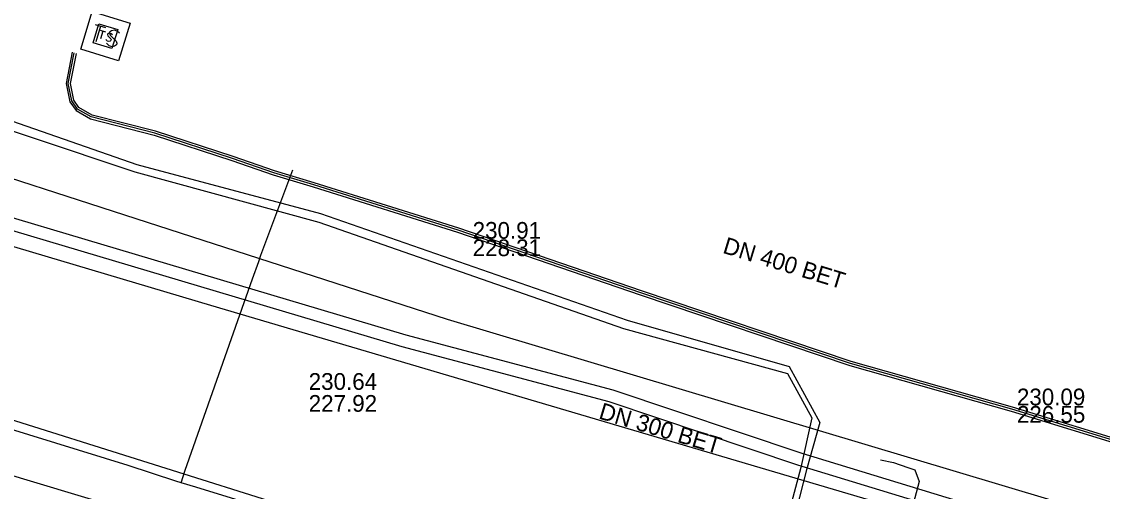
# Model space of a CAD drawing. Extents: x -599951 to -598963, y -1164095 to -1162939.
# Drawn here: x -599654.3 to -599602.6, y -1164052.7 to -1164030.3 of the extents above; entities that cross this region are included whole.
import ezdxf

# ---------------------------------------------------------------- set-up
doc = ezdxf.new("R2010")
doc.units = 0
for name, color, linetype in [('25', 7, 'Continuous'), ('Level 3', 7, 'Continuous'), ('Vrstva 1', 7, 'Continuous'), ('Vrstva 12', 7, 'Continuous'), ('Vrstva 13', 7, 'Continuous'), ('Vrstva 16', 7, 'Continuous'), ('Vrstva 19', 7, 'Continuous'), ('Vrstva 4', 7, 'Continuous'), ('Vrstva 42', 7, 'Continuous'), ('Vrstva 43', 7, 'Continuous'), ('Vrstva 44', 7, 'Continuous'), ('Vrstva 45', 7, 'Continuous'), ('Vrstva 5', 7, 'Continuous'), ('Vrstva 8', 7, 'Continuous')]:
    doc.layers.add(name, color=color, linetype=linetype)

# ---------------------------------------------------------------- blocks, each defined once
blk = doc.blocks.new('VN640')
at = {"layer": '25'}
for points in [[(-1.89, 1.889), (1.889, 1.889)], [(-1.89, -1.89), (-1.89, 1.889)], [(-1.26, 0.787), (-0.221, 0.787)], [(-0.725, 0.787), (-0.725, -0.788)], [(1.197, 0.661), (0.945, 0.787), (0.661, 0.787), (0.409, 0.661), (0.283, 0.472), (0.283, 0.409), (0.409, 0.22), (1.133, -0.158), (1.259, -0.316), (1.259, -0.473), (1.133, -0.662), (0.913, -0.788), (0.629, -0.788), (0.503, -0.725), (0.283, -0.599)], [(1.889, 1.889), (1.889, -1.89)], [(1.889, -1.89), (-1.89, -1.89)]]:
    blk.add_lwpolyline(points, dxfattribs=at)
blk = doc.blocks.new('NN640')
at = {"layer": '25'}
for points in [[(-1.89, 1.889), (1.889, 1.889)], [(-1.89, -1.89), (-1.89, 1.889)], [(1.889, 1.889), (1.889, -1.89)], [(-1.26, 0.787), (-0.221, 0.787)], [(-0.725, 0.787), (-0.725, -0.788)], [(1.197, 0.661), (0.945, 0.787), (0.661, 0.787), (0.409, 0.661), (0.283, 0.472), (0.283, 0.409), (0.409, 0.22), (1.133, -0.158), (1.259, -0.316), (1.259, -0.473), (1.133, -0.662), (0.913, -0.788), (0.629, -0.788), (0.503, -0.725), (0.283, -0.599)], [(1.889, -1.89), (-1.89, -1.89)]]:
    blk.add_lwpolyline(points, dxfattribs=at)

msp = doc.modelspace()

# ---------------------------------------------------------------- linework, layer by layer
at = {"layer": 'Level 3'}
msp.add_lwpolyline([(-599670.761, -1164034.874), (-599635.968, -1164045.241), (-599626.064, -1164047.883), (-599617.019, -1164050.914), (-599600, -1164056.104), (-599591.155, -1164058.802), (-599583.98, -1164060.87), (-599584.17, -1164061.41), (-599591.325, -1164059.378), (-599600, -1164056.732), (-599617.201, -1164051.486), (-599626.236, -1164048.457), (-599636.132, -1164045.819), (-599670.939, -1164035.446)], dxfattribs=at)
at = {"layer": 'Vrstva 1'}
msp.add_line((-599684.011, -1164040.127), (-599641.114, -1164053.622), dxfattribs=at)
at = {"layer": 'Vrstva 12'}
for points in [[(-599611.95, -1164051.59), (-599611.61, -1164051.71), (-599611.4, -1164052.26), (-599614.05, -1164062.23), (-599613.46, -1164062.85)], [(-599613.25, -1164051.23), (-599612.63, -1164051.36), (-599611.95, -1164051.59)]]:
    msp.add_lwpolyline(points, dxfattribs=at)
at = {"layer": 'Vrstva 13'}
msp.add_lwpolyline([(-599708, -1164025.26), (-599702.264, -1164026.912), (-599699.155, -1164027.826), (-599681.16, -1164033.15), (-599677.61, -1164034.2), (-599645.3, -1164043.83), (-599608.77, -1164054.62)], dxfattribs=at)
at = {"layer": 'Vrstva 16'}
msp.add_lwpolyline([(-599532.23, -1164094.695), (-599576.26, -1164075.92), (-599581.33, -1164074.29), (-599595.84, -1164069.64), (-599596.96, -1164069.28), (-599602.44, -1164067.76), (-599618.73, -1164062.85), (-599666.38, -1164048.5), (-599672.28, -1164046.86), (-599687.99, -1164042.5)], dxfattribs=at)
at = {"layer": 'Vrstva 19'}
for points in [[(-599646.71, -1164052.33), (-599646.51, -1164051.73), (-599643.293, -1164042.566), (-599643, -1164041.73), (-599642.9, -1164041.43), (-599641.37, -1164037.35)], [(-599517.408, -1164094.695), (-599537.5, -1164086.87), (-599571.84, -1164074.84), (-599589.93, -1164069.71), (-599590.38, -1164069.57), (-599590.89, -1164069.41), (-599601.93, -1164066.13), (-599608.97, -1164063.96), (-599646.01, -1164052.54), (-599646.71, -1164052.33), (-599646.97, -1164052.25), (-599649.244, -1164051.504), (-599665.68, -1164046.42), (-599687.59, -1164039.86)]]:
    msp.add_lwpolyline(points, dxfattribs=at)
at = {"layer": 'Vrstva 42'}
for points in [[(-599667, -1163993.46), (-599669.9, -1164004.29), (-599672.49, -1164011.1), (-599676.75, -1164026.4), (-599676.92, -1164027.5), (-599676.41, -1164028.19), (-599669.7, -1164030.95), (-599658.77, -1164034.16), (-599648.93, -1164037.44), (-599640.13, -1164039.85), (-599625.55, -1164044.94), (-599617.7, -1164047.09), (-599616.53, -1164049.22), (-599617.07, -1164051.6), (-599619.484, -1164060.682), (-599619.155, -1164061.753), (-599619.572, -1164062.391)], [(-599666.6, -1163993.43), (-599669.67, -1164004.37), (-599672.17, -1164011.18), (-599676.46, -1164026.39), (-599676.53, -1164027.48), (-599676.13, -1164027.87), (-599669.65, -1164030.47), (-599658.68, -1164033.66), (-599648.83, -1164037.1), (-599640.04, -1164039.44), (-599625.37, -1164044.54), (-599617.62, -1164046.76), (-599616.16, -1164049.44), (-599616.79, -1164051.7), (-599619.103, -1164060.744), (-599618.903, -1164061.834), (-599619.388, -1164062.469)]]:
    msp.add_lwpolyline(points, dxfattribs=at)
at = {"layer": 'Vrstva 44'}
for p, q in [((-599652.11, -1164033.22), (-599651.82, -1164031.75)), ((-599651.94, -1164034.05), (-599652.11, -1164033.22)), ((-599651.67, -1164034.44), (-599651.94, -1164034.05)), ((-599651.01, -1164034.82), (-599651.67, -1164034.44)), ((-599647.97, -1164035.6), (-599651.01, -1164034.82)), ((-599644.26, -1164036.8), (-599647.97, -1164035.6)), ((-599642.27, -1164037.5), (-599644.26, -1164036.8)), ((-599640.37, -1164038.07), (-599642.27, -1164037.5)), ((-599633.45, -1164040.23), (-599640.37, -1164038.07)), ((-599624.72, -1164043.23), (-599633.45, -1164040.23)), ((-599614.69, -1164046.62), (-599624.72, -1164043.23)), ((-599606.97, -1164048.81), (-599614.69, -1164046.62)), ((-599601.05, -1164050.62), (-599606.97, -1164048.81))]:
    msp.add_line(p, q, dxfattribs=at)
for points in [[(-599651.916, -1164031.719), (-599652.212, -1164033.22), (-599652.034, -1164034.09), (-599651.739, -1164034.515), (-599651.048, -1164034.913), (-599647.998, -1164035.696), (-599644.292, -1164036.895), (-599642.301, -1164037.595), (-599640.399, -1164038.166), (-599633.481, -1164040.325), (-599624.752, -1164043.325), (-599614.72, -1164046.716), (-599606.998, -1164048.906), (-599601.079, -1164050.716)], [(-599592.804, -1164051.197), (-599593.016, -1164051.8), (-599593.3, -1164052.33), (-599593.74, -1164052.57), (-599594.247, -1164052.645), (-599594.584, -1164052.607), (-599595.777, -1164052.146), (-599601.021, -1164050.524), (-599606.942, -1164048.714), (-599614.66, -1164046.524), (-599624.688, -1164043.135), (-599633.419, -1164040.135), (-599640.341, -1164037.974), (-599642.239, -1164037.405), (-599644.228, -1164036.705), (-599647.942, -1164035.504), (-599650.972, -1164034.727), (-599651.601, -1164034.365), (-599651.846, -1164034.01), (-599652.008, -1164033.22), (-599651.724, -1164031.781)]]:
    msp.add_lwpolyline(points, dxfattribs=at)
at = {"layer": 'Vrstva 5'}
msp.add_line((-599633.99, -1164044.5), (-599602.92, -1164053.79), dxfattribs=at)
msp.add_lwpolyline([(-599676.979, -1164030.579), (-599648.877, -1164039.676), (-599633.99, -1164044.5)], dxfattribs=at)

# ---------------------------------------------------------------- block references
at = {"layer": 'Vrstva 43', "xscale": 0.5000000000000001, "yscale": 0.5, "rotation": -17.000000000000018}
msp.add_blockref('NN640', (-599650.336, -1164030.952), dxfattribs=at)
at = {"layer": 'Vrstva 45', "xscale": 0.25, "yscale": 0.25, "rotation": -17.00000000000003}
msp.add_blockref('VN640', (-599650.336, -1164030.952), dxfattribs=at)

# ---------------------------------------------------------------- texts
at = {"layer": 'Vrstva 4'}
for s, p in [('230.91', (-599632.763, -1164040.647)), ('228.31', (-599632.763, -1164041.479)), ('230.09', (-599606.727, -1164048.62)), ('226.55', (-599606.727, -1164049.452))]:
    msp.add_text(s, height=0.8, dxfattribs=at).set_placement(p)
msp.add_text('DN 400 BET', height=0.8, rotation=343.0352, dxfattribs=at).set_placement((-599620.843, -1164041.316))
at = {"layer": 'Vrstva 8'}
for s, p in [('230.64', (-599640.607, -1164047.879)), ('227.92', (-599640.607, -1164048.929))]:
    msp.add_text(s, height=0.8, dxfattribs=at).set_placement(p)
msp.add_text('DN 300 BET', height=0.8, rotation=343.3532, dxfattribs=at).set_placement((-599626.776, -1164049.243))

doc.saveas('drawing.dxf')
